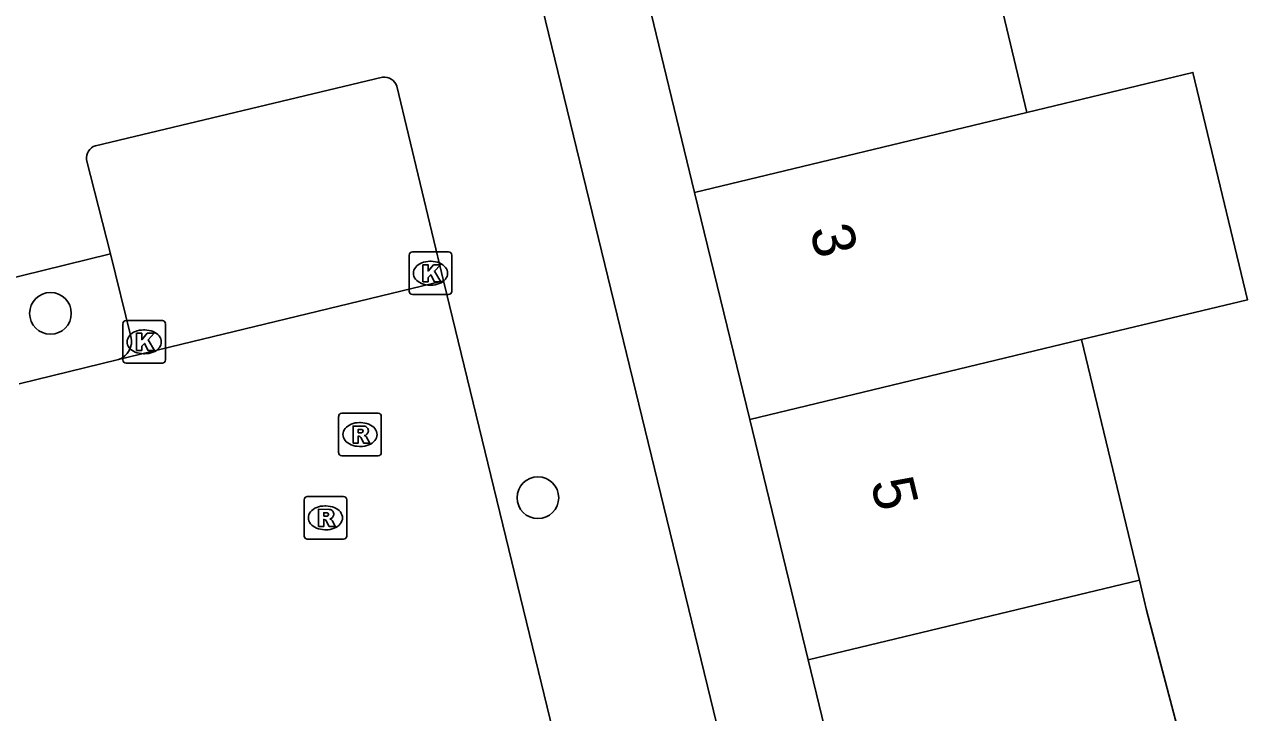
# Model space of a CAD drawing. Extents: x 159718 to 160783, y 383290 to 384030.
# Drawn here: x 160224.66 to 160253.37, y 383519.16 to 383535.3 of the extents above; entities that cross this region are included whole.
import ezdxf

# ---------------------------------------------------------------- set-up
doc = ezdxf.new("R2010")
doc.units = 0
for name, color, linetype in [('IMGEO_Boom', 7, 'Continuous'), ('IMGEO_Kolk', 7, 'Continuous'), ('IMGEO_Pand', 7, 'Continuous'), ('IMGEO_Pand_nummerreeks', 7, 'Continuous'), ('IMGEO_Parkeervlak_open', 7, 'Continuous'), ('IMGEO_Rijbaan_lokaal_open', 7, 'Continuous'), ('IMGEO_Rioolput', 7, 'Continuous'), ('IMGEO_Voetpad_open', 7, 'Continuous')]:
    doc.layers.add(name, color=color, linetype=linetype)

msp = doc.modelspace()

# ---------------------------------------------------------------- linework, layer by layer
at = {"layer": 'IMGEO_Boom'}
for centre in [(160225.271, 383528.524), (160236.713, 383524.201)]:
    msp.add_circle(centre, 0.489, dxfattribs=at)
at = {"layer": 'IMGEO_Kolk'}
for p, q in [((160233.691, 383529.04), (160233.691, 383529.892)), ((160233.766, 383529.966), (160234.618, 383529.966)), ((160234.692, 383529.892), (160234.692, 383529.04)), ((160234.179, 383529.746), (160234.204, 383529.746)), ((160234.202, 383529.186), (160234.177, 383529.186)), ((160234.618, 383528.966), (160233.766, 383528.966)), ((160226.97, 383527.431), (160226.97, 383528.283)), ((160227.045, 383528.357), (160227.897, 383528.357)), ((160227.971, 383528.283), (160227.971, 383527.431)), ((160227.458, 383528.137), (160227.483, 383528.137)), ((160227.897, 383527.357), (160227.045, 383527.357)), ((160227.481, 383527.577), (160227.456, 383527.577))]:
    msp.add_line(p, q, dxfattribs=at)
for points in [[(160233.691, 383529.04), (160233.691, 383529.892)], [(160233.766, 383529.966), (160234.618, 383529.966)], [(160234.692, 383529.892), (160234.692, 383529.04)], [(160234.012, 383529.666), (160234.135, 383529.666), (160234.135, 383529.515), (160234.265, 383529.666), (160234.429, 383529.666), (160234.283, 383529.515), (160234.436, 383529.266), (160234.284, 383529.266), (160234.199, 383529.43), (160234.135, 383529.363), (160234.135, 383529.266), (160234.012, 383529.266), (160234.012, 383529.666)], [(160234.618, 383528.966), (160233.766, 383528.966)], [(160226.97, 383527.431), (160226.97, 383528.283)], [(160227.045, 383528.357), (160227.897, 383528.357)], [(160227.971, 383528.283), (160227.971, 383527.431)], [(160227.291, 383528.057), (160227.414, 383528.057), (160227.414, 383527.906), (160227.544, 383528.057), (160227.708, 383528.057), (160227.562, 383527.906), (160227.715, 383527.657), (160227.563, 383527.657), (160227.478, 383527.821), (160227.414, 383527.754), (160227.414, 383527.657), (160227.291, 383527.657), (160227.291, 383528.057)], [(160227.897, 383527.357), (160227.045, 383527.357)]]:
    msp.add_lwpolyline(points, dxfattribs=at)
for centre, start, end in [((160233.768, 383529.89), 91.552, 178.448), ((160233.768, 383529.89), 91.552, 178.448), ((160234.616, 383529.89), 1.552, 88.448), ((160234.616, 383529.89), 1.552, 88.448), ((160233.768, 383529.042), 181.552, 268.448), ((160233.768, 383529.042), 181.552, 268.448), ((160234.616, 383529.042), 271.552, 358.448), ((160234.616, 383529.042), 271.552, 358.448), ((160227.047, 383528.281), 91.552, 178.448), ((160227.047, 383528.281), 91.552, 178.448), ((160227.895, 383528.281), 1.552, 88.448), ((160227.895, 383528.281), 1.552, 88.448), ((160227.047, 383527.433), 181.552, 268.448), ((160227.047, 383527.433), 181.552, 268.448), ((160227.895, 383527.433), 271.552, 358.448), ((160227.895, 383527.433), 271.552, 358.448)]:
    msp.add_arc(centre, 0.0765, start, end, dxfattribs=at)
for centre, major_axis, ratio, start_param, end_param in [((160234.178, 383529.466), (-0.387, 0.002), 0.722429, 4.712389, 7.853982), ((160234.203, 383529.466), (-0.39, 0.002), 0.717154, 1.570796, 4.712389), ((160227.457, 383527.857), (-0.387, 0.002), 0.722429, 4.712389, 7.853982), ((160227.482, 383527.857), (-0.39, 0.002), 0.717154, 1.570796, 4.712389)]:
    msp.add_ellipse(centre, major_axis=major_axis, ratio=ratio, start_param=start_param, end_param=end_param, dxfattribs=at)
at = {"layer": 'IMGEO_Pand'}
for points in [[(160240.391, 383531.362), (160239.188, 383536.311), (160238.978, 383537.176), (160239.27, 383537.247), (160238.915, 383538.705), (160245.816, 383540.381), (160246.193, 383538.813), (160246.817, 383538.963), (160248.194, 383533.238)], [(160248.194, 383533.238), (160252.089, 383534.175), (160253.371, 383528.845), (160249.476, 383527.908)], [(160248.194, 383533.238), (160240.391, 383531.362)], [(160241.686, 383526.035), (160240.391, 383531.362)], [(160241.686, 383526.035), (160249.476, 383527.908)], [(160249.476, 383527.908), (160250.833, 383522.268)], [(160243.056, 383520.398), (160241.686, 383526.035)], [(160250.833, 383522.268), (160251.002, 383521.564), (160252.269, 383516.763), (160244.402, 383514.857), (160243.056, 383520.398)], [(160243.056, 383520.398), (160250.833, 383522.268)]]:
    msp.add_lwpolyline(points, dxfattribs=at)
at = {"layer": 'IMGEO_Parkeervlak_open'}
msp.add_lwpolyline([(160226.678, 383529.92), (160227.161, 383527.985)], dxfattribs=at)
msp.add_arc((160226.719, 383527.873), 0.456, 288.649, 14.2482, dxfattribs=at)
at = {"layer": 'IMGEO_Rijbaan_lokaal_open'}
for points in [[(160226.865, 383527.441), (160234.497, 383529.288)], [(160234.497, 383529.288), (160237.139, 383518.423)], [(160224.539, 383526.869), (160226.865, 383527.441)]]:
    msp.add_lwpolyline(points, dxfattribs=at)
at = {"layer": 'IMGEO_Rioolput'}
for p, q in [((160232.111, 383526.183), (160232.963, 383526.183)), ((160232.036, 383525.257), (160232.036, 383526.109)), ((160232.524, 383525.963), (160232.549, 383525.963)), ((160233.037, 383526.109), (160233.037, 383525.257)), ((160232.547, 383525.403), (160232.522, 383525.403)), ((160232.963, 383525.183), (160232.111, 383525.183)), ((160231.225, 383523.303), (160231.225, 383524.155)), ((160231.3, 383524.229), (160232.152, 383524.229)), ((160232.226, 383524.155), (160232.226, 383523.303)), ((160231.713, 383524.009), (160231.738, 383524.009)), ((160231.736, 383523.449), (160231.711, 383523.449)), ((160232.152, 383523.229), (160231.3, 383523.229))]:
    msp.add_line(p, q, dxfattribs=at)
for points in [[(160232.111, 383526.183), (160232.963, 383526.183)], [(160232.036, 383525.257), (160232.036, 383526.109)], [(160232.625, 383525.881), (160232.373, 383525.883), (160232.373, 383525.483)], [(160233.037, 383526.109), (160233.037, 383525.257)], [(160232.373, 383525.483), (160232.497, 383525.483), (160232.497, 383525.645), (160232.508, 383525.645)], [(160232.551, 383525.802), (160232.497, 383525.802), (160232.497, 383525.721)], [(160232.497, 383525.721), (160232.549, 383525.721)], [(160232.555, 383525.616), (160232.626, 383525.483), (160232.766, 383525.483), (160232.701, 383525.609)], [(160232.963, 383525.183), (160232.111, 383525.183)], [(160231.225, 383523.303), (160231.225, 383524.155)], [(160231.3, 383524.229), (160232.152, 383524.229)], [(160232.226, 383524.155), (160232.226, 383523.303)], [(160231.814, 383523.927), (160231.562, 383523.929), (160231.562, 383523.529)], [(160231.562, 383523.529), (160231.686, 383523.529), (160231.686, 383523.691), (160231.697, 383523.691)], [(160231.74, 383523.848), (160231.686, 383523.848), (160231.686, 383523.767)], [(160231.686, 383523.767), (160231.738, 383523.767)], [(160231.744, 383523.662), (160231.815, 383523.529), (160231.955, 383523.529), (160231.89, 383523.655)], [(160232.152, 383523.229), (160231.3, 383523.229)]]:
    msp.add_lwpolyline(points, dxfattribs=at)
for centre, radius, start, end in [((160232.113, 383526.107), 0.0765, 91.552, 178.448), ((160232.113, 383526.107), 0.0765, 91.552, 178.448), ((160232.961, 383526.107), 0.0765, 1.552, 88.448), ((160232.961, 383526.107), 0.0765, 1.552, 88.448), ((160232.624, 383525.771), 0.109, 350.3612, 89.416), ((160232.507, 383525.592), 0.0533, 26.0293, 88.6989), ((160232.533, 383525.91), 0.19, 274.7715, 282.9687), ((160232.557, 383525.706), 0.0964, 77.0061, 93.1865), ((160232.571, 383525.763), 0.0378, 276.6634, 79.6772), ((160232.622, 383525.771), 0.112, 277.5842, 350.9817), ((160232.606, 383525.556), 0.108, 29.5134, 73.7905), ((160232.113, 383525.259), 0.0765, 181.552, 268.448), ((160232.113, 383525.259), 0.0765, 181.552, 268.448), ((160232.961, 383525.259), 0.0765, 271.552, 358.448), ((160232.961, 383525.259), 0.0765, 271.552, 358.448), ((160231.302, 383524.153), 0.0765, 91.552, 178.448), ((160231.302, 383524.153), 0.0765, 91.552, 178.448), ((160232.15, 383524.153), 0.0765, 1.552, 88.448), ((160232.15, 383524.153), 0.0765, 1.552, 88.448), ((160231.813, 383523.817), 0.109, 350.3612, 89.416), ((160231.696, 383523.638), 0.0533, 26.0293, 88.6989), ((160231.722, 383523.956), 0.19, 274.7715, 282.9687), ((160231.746, 383523.752), 0.0964, 77.0061, 93.1865), ((160231.76, 383523.809), 0.0378, 276.6634, 79.6772), ((160231.811, 383523.817), 0.112, 277.5842, 350.9817), ((160231.795, 383523.602), 0.108, 29.5134, 73.7905), ((160231.302, 383523.305), 0.0765, 181.552, 268.448), ((160231.302, 383523.305), 0.0765, 181.552, 268.448), ((160232.15, 383523.305), 0.0765, 271.552, 358.448), ((160232.15, 383523.305), 0.0765, 271.552, 358.448)]:
    msp.add_arc(centre, radius, start, end, dxfattribs=at)
for centre, major_axis, ratio, start_param, end_param in [((160232.523, 383525.683), (-0.387, 0.002), 0.722429, 4.712389, 7.853982), ((160232.548, 383525.683), (-0.39, 0.002), 0.717154, 1.570796, 4.712389), ((160231.712, 383523.729), (-0.387, 0.002), 0.722429, 4.712389, 7.853982), ((160231.737, 383523.729), (-0.39, 0.002), 0.717154, 1.570796, 4.712389)]:
    msp.add_ellipse(centre, major_axis=major_axis, ratio=ratio, start_param=start_param, end_param=end_param, dxfattribs=at)
at = {"layer": 'IMGEO_Voetpad_open'}
for points in [[(160225.103, 383536.646), (160225.36, 383535.533), (160236.232, 383538.092), (160242.449, 383512.59)], [(160233.068, 383534.062), (160226.327, 383532.456)], [(160234.497, 383529.288), (160233.4, 383533.854)], [(160226.119, 383532.124), (160226.678, 383529.92)], [(160226.678, 383529.92), (160223.528, 383529.146)]]:
    msp.add_lwpolyline(points, dxfattribs=at)
for centre, radius, start, end in [((160233.113, 383533.765), 0.3, 17.1854, 98.6798), ((160226.42, 383532.167), 0.304, 107.7439, 188.1213)]:
    msp.add_arc(centre, radius, start, end, dxfattribs=at)

# ---------------------------------------------------------------- texts
at = {"layer": 'IMGEO_Pand_nummerreeks'}
for s, p in [('3', (160243.093, 383530.49)), ('5', (160244.52, 383524.558))]:
    msp.add_text(s, height=1, rotation=283.5273, dxfattribs=at).set_placement(p)

doc.saveas('drawing.dxf')
